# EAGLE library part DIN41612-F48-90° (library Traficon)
Harting 09-06-248-7836 or 09-06-248-6836
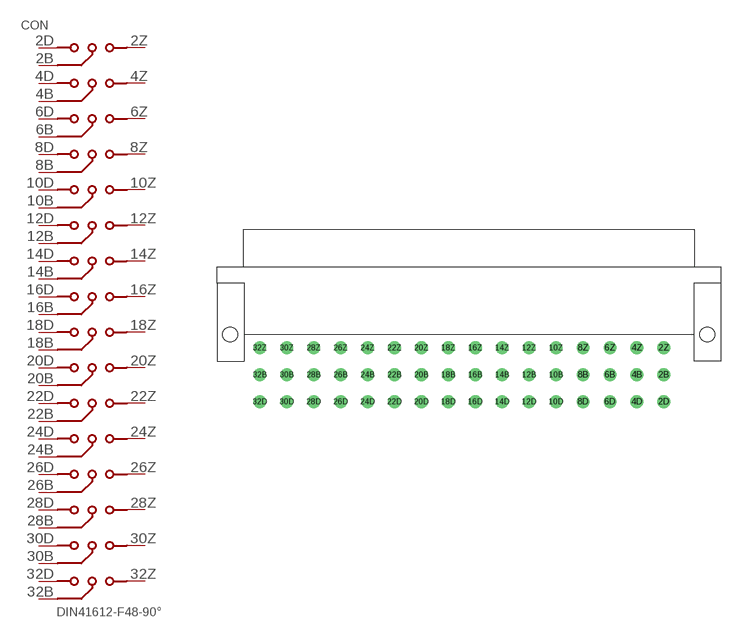
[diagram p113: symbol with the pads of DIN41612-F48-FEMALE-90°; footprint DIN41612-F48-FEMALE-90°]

Designator prefix CON

## DIN41612-F48-90°  [DIN41612-F48-FEMALE-90°]
2B  2B
2D  2D
2Z  2Z
4B  4B
4D  4D
4Z  4Z
6B  6B
6D  6D
6Z  6Z
8B  8B
8D  8D
8Z  8Z
10B  10B
10D  10D
10Z  10Z
12B  12B
12D  12D
12Z  12Z
14B  14B
14D  14D
14Z  14Z
16B  16B
16D  16D
16Z  16Z
18B  18B
18D  18D
18Z  18Z
20B  20B
20D  20D
20Z  20Z
22B  22B
22D  22D
22Z  22Z
24B  24B
24D  24D
24Z  24Z
26B  26B
26D  26D
26Z  26Z
28B  28B
28D  28D
28Z  28Z
30B  30B
30D  30D
30Z  30Z
32B  32B
32D  32D
32Z  32Z

## Footprint DIN41612-F48-FEMALE-90° (pad centres in mm)
drill 1.6 round: 2B 36.83,-11.43; 2D 36.83,-16.51; 2Z 36.83,-6.35; 4B 31.75,-11.43; 4D 31.75,-16.51; 4Z 31.75,-6.35; 6B 26.67,-11.43; 6D 26.67,-16.51; 6Z 26.67,-6.35; 8B 21.59,-11.43; 8D 21.59,-16.51; 8Z 21.59,-6.35; 10B 16.51,-11.43; 10D 16.51,-16.51; 10Z 16.51,-6.35; 12B 11.43,-11.43; 12D 11.43,-16.51; 12Z 11.43,-6.35; 14B 6.35,-11.43; 14D 6.35,-16.51; 14Z 6.35,-6.35; 16B 1.27,-11.43; 16D 1.27,-16.51; 16Z 1.27,-6.35; 18B -3.81,-11.43; 18D -3.81,-16.51; 18Z -3.81,-6.35; 20B -8.89,-11.43; 20D -8.89,-16.51; 20Z -8.89,-6.35; 22B -13.97,-11.43; 22D -13.97,-16.51; 22Z -13.97,-6.35; 24B -19.05,-11.43; 24D -19.05,-16.51; 24Z -19.05,-6.35; 26B -24.13,-11.43; 26D -24.13,-16.51; 26Z -24.13,-6.35; 28B -29.21,-11.43; 28D -29.21,-16.51; 28Z -29.21,-6.35; 30B -34.29,-11.43; 30D -34.29,-16.51; 30Z -34.29,-6.35; 32B -39.37,-11.43; 32D -39.37,-16.51; 32Z -39.37,-6.35
hole 2.8 at -45,-3.85
hole 2.8 at 45,-3.85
